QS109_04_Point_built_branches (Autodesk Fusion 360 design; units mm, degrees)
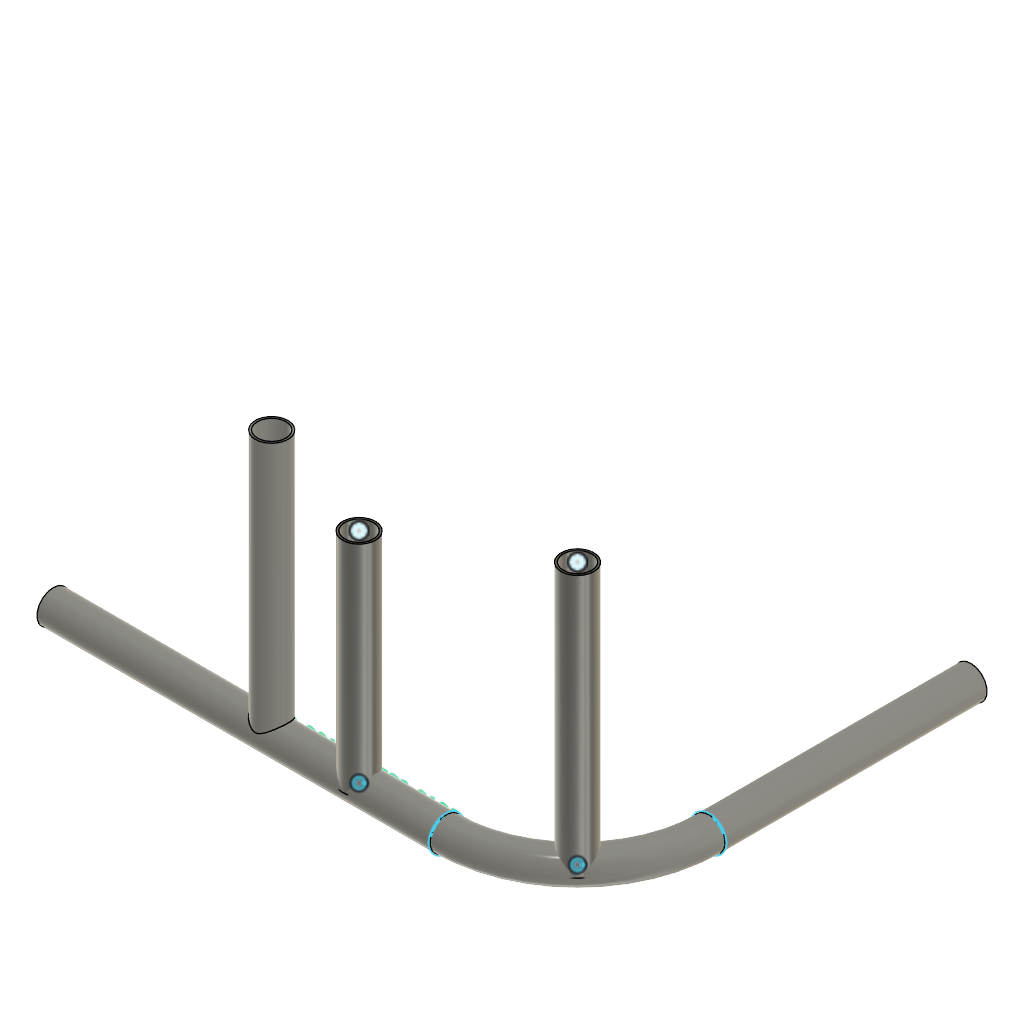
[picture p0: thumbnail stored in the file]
description: Part Number
part number: 2026-10-26-11-38-19-526
parameter "OD_DEMO_ONLY_1_5_x_095_R6" = 38.1
parameter "Wall_DEMO_ONLY_1_5_x_095_R6" = 2.413
base_feature "Base Feature" bodies "H1 Bent host", "I1 Imported coped brace"
sketch "Tube points" plane through (0, 0, 0) normal (0, 0, 1) x axis (1, 0, 0)
sketch "TubePoints" plane through (0, 0, 0) normal (0, 0, 1) x axis (1, 0, 0)
work_plane "WorkPlane1" ExtraOffset 0
sketch "Sketch3" plane through (564.9631, 44.6369, 0) normal (0, 0, 1) x axis (0, 1, 0)
  circle C1 centre (0, 0) radius 19.05
  circle C2 centre (0, 0) radius 16.637
sketch "TubePoints (1)" plane through (0, 0, 0) normal (0, 0, 1) x axis (1, 0, 0)
work_plane "WorkPlane2" ExtraOffset 0
sketch "Sketch5" plane through (355.6, 0, 0) normal (0, 0, 1) x axis (0, 1, 0)
  circle C1 centre (0, 0) radius 19.05
  circle C2 centre (0, 0) radius 16.637
sketch "TubePoints (2)" plane through (0, 0, 0) normal (0, 0, 1) x axis (1, 0, 0)
work_plane "WorkPlane3" ExtraOffset 0
sketch "Sketch7" plane through (564.9631, 44.6369, 0) normal (0, 0, 1) x axis (0, 1, 0)
  circle C1 centre (0, 0) radius 19.05
  circle C2 centre (0, 0) radius 16.637
  dimension "d21" diameter C1 = 38.1 (= "OD_DEMO_ONLY_1_5_x_095_R6")
  dimension "d22" diameter C2 = 33.274 (= "OD_DEMO_ONLY_1_5_x_095_R6 - 2 * Wall_DEMO_ONLY_1_5_x_095_R6")
sweep "Sweep3" sketch "Sketch7" TwistAngle 0 TaperAngle 0 bodies "B1 Bend follower"
sketch "TubePoints (3)" plane through (0, 0, 0) normal (0, 0, 1) x axis (1, 0, 0)
work_plane "WorkPlane4" ExtraOffset 0
sketch "Sketch9" plane through (355.6, 0, 0) normal (0, 0, 1) x axis (0, 1, 0)
  circle C1 centre (0, 0) radius 19.05
  circle C2 centre (0, 0) radius 16.637
  dimension "d31" diameter C1 = 38.1 (= "OD_DEMO_ONLY_1_5_x_095_R6")
  dimension "d32" diameter C2 = 33.274 (= "OD_DEMO_ONLY_1_5_x_095_R6 - 2 * Wall_DEMO_ONLY_1_5_x_095_R6")
sweep "Sweep4" sketch "Sketch9" TwistAngle 0 TaperAngle 0 bodies "B2 Straight joint"
named bodies: "H1 Bent host", "I1 Imported coped brace", "B1 Bend follower", "B2 Straight joint"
